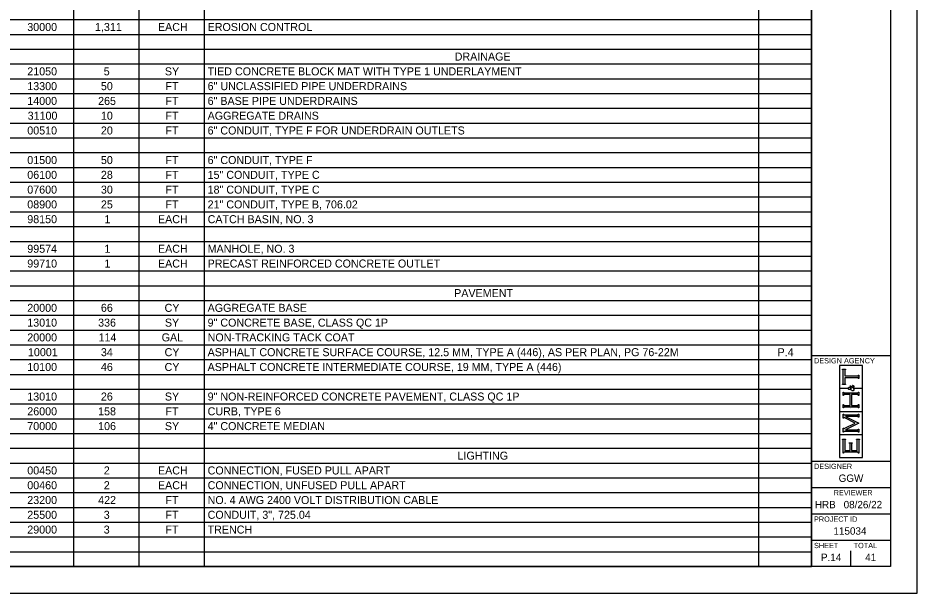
# Model space of a CAD drawing. Extents: x 0 to 34, y 0 to 22.
# Drawn here: x 16.98 to 34, y 0 to 10.89 of the extents above; entities that cross this region are included whole.
import ezdxf

# ---------------------------------------------------------------- set-up
doc = ezdxf.new("R2010")
doc.units = 0
for name, color, linetype in [('SH_Border', 7, 'Continuous'), ('SH_Cut_Line', 7, 'Continuous'), ('SH_Data', 7, 'Continuous'), ('SH_Text', 7, 'Continuous')]:
    doc.layers.add(name, color=color, linetype=linetype)

msp = doc.modelspace()

# ---------------------------------------------------------------- linework, layer by layer
at = {"layer": 'SH_Border'}
for p, q in [((32, 0.5), (32, 21.5)), ((32, 4.5), (33.5, 4.5)), ((32, 2.5), (33.5, 2.5)), ((32, 2), (33.5, 2)), ((32, 1.5), (33.5, 1.5)), ((32, 1), (33.5, 1))]:
    msp.add_line(p, q, dxfattribs=at)
msp.add_lwpolyline([(1.5, 21.5), (33.5, 21.5), (33.5, 0.5), (1.5, 0.5)], close=True, dxfattribs=at)
at = {"layer": 'SH_Cut_Line'}
msp.add_lwpolyline([(0, 0), (34, 0), (34, 22), (0, 22)], close=True, dxfattribs=at)
at = {"layer": 'SH_Data'}
for p, q in [((32.966, 4.31), (32.534, 4.31)), ((32.534, 4.31), (32.534, 3.878)), ((32.966, 3.878), (32.966, 4.31)), ((32.588, 4.23), (32.588, 4.237)), ((32.588, 4.237), (32.644, 4.237)), ((32.594, 4.228), (32.588, 4.23)), ((32.598, 4.227), (32.594, 4.228)), ((32.599, 4.224), (32.598, 4.227)), ((32.601, 4.221), (32.599, 4.224)), ((32.602, 4.217), (32.601, 4.221)), ((32.602, 4.211), (32.602, 4.217)), ((32.602, 3.977), (32.602, 4.211)), ((32.632, 4.221), (32.631, 4.217)), ((32.631, 4.217), (32.631, 4.211)), ((32.631, 4.211), (32.631, 4.111)), ((32.631, 4.111), (32.872, 4.111)), ((32.633, 4.224), (32.632, 4.221)), ((32.635, 4.227), (32.633, 4.224)), ((32.639, 4.228), (32.635, 4.227)), ((32.644, 4.23), (32.639, 4.228)), ((32.644, 4.237), (32.644, 4.23)), ((32.872, 4.111), (32.878, 4.111)), ((32.878, 4.111), (32.882, 4.112)), ((32.882, 4.112), (32.885, 4.114)), ((32.885, 4.114), (32.887, 4.116)), ((32.887, 4.116), (32.889, 4.12)), ((32.889, 4.12), (32.891, 4.125)), ((32.891, 4.125), (32.898, 4.125)), ((32.898, 4.125), (32.898, 4.063)), ((32.588, 3.959), (32.594, 3.96)), ((32.588, 3.952), (32.588, 3.959)), ((32.644, 3.952), (32.588, 3.952)), ((32.594, 3.96), (32.598, 3.962)), ((32.598, 3.962), (32.599, 3.964)), ((32.599, 3.964), (32.601, 3.967)), ((32.601, 3.967), (32.602, 3.971)), ((32.602, 3.971), (32.602, 3.977)), ((32.872, 4.077), (32.631, 4.077)), ((32.631, 4.077), (32.631, 3.977)), ((32.631, 3.977), (32.631, 3.971)), ((32.631, 3.971), (32.632, 3.967)), ((32.632, 3.967), (32.633, 3.964)), ((32.633, 3.964), (32.635, 3.962)), ((32.635, 3.962), (32.639, 3.96)), ((32.639, 3.96), (32.644, 3.959)), ((32.644, 3.959), (32.644, 3.952)), ((32.738, 3.898), (32.738, 3.928)), ((32.738, 3.928), (32.741, 3.928)), ((32.741, 3.928), (32.741, 3.924)), ((32.741, 3.924), (32.742, 3.921)), ((32.742, 3.921), (32.744, 3.919)), ((32.744, 3.919), (32.745, 3.917)), ((32.745, 3.917), (32.75, 3.914)), ((32.781, 3.93), (32.783, 3.933)), ((32.785, 3.929), (32.781, 3.93)), ((32.783, 3.933), (32.79, 3.931)), ((32.788, 3.927), (32.785, 3.929)), ((32.789, 3.925), (32.788, 3.927)), ((32.791, 3.923), (32.789, 3.925)), ((32.79, 3.931), (32.795, 3.928)), ((32.792, 3.92), (32.791, 3.923)), ((32.792, 3.917), (32.792, 3.92)), ((32.792, 3.913), (32.792, 3.917)), ((32.795, 3.928), (32.799, 3.924)), ((32.799, 3.924), (32.802, 3.92)), ((32.802, 3.92), (32.803, 3.916)), ((32.803, 3.916), (32.803, 3.91)), ((32.878, 4.077), (32.872, 4.077)), ((32.883, 4.076), (32.878, 4.077)), ((32.885, 4.074), (32.883, 4.076)), ((32.888, 4.073), (32.885, 4.074)), ((32.889, 4.069), (32.888, 4.073)), ((32.891, 4.063), (32.889, 4.069)), ((32.898, 4.063), (32.891, 4.063)), ((32.534, 3.878), (32.693, 3.878)), ((32.693, 3.873), (32.534, 3.873)), ((32.534, 3.873), (32.534, 3.441)), ((32.602, 3.744), (32.602, 3.806)), ((32.602, 3.806), (32.609, 3.806)), ((32.609, 3.744), (32.602, 3.744)), ((32.609, 3.806), (32.611, 3.801)), ((32.61, 3.75), (32.609, 3.744)), ((32.612, 3.754), (32.61, 3.75)), ((32.611, 3.801), (32.612, 3.797)), ((32.612, 3.797), (32.615, 3.795)), ((32.615, 3.755), (32.612, 3.754)), ((32.615, 3.795), (32.617, 3.793)), ((32.617, 3.757), (32.615, 3.755)), ((32.617, 3.793), (32.622, 3.792)), ((32.622, 3.758), (32.617, 3.757)), ((32.622, 3.792), (32.628, 3.792)), ((32.628, 3.758), (32.622, 3.758)), ((32.628, 3.792), (32.872, 3.792)), ((32.732, 3.758), (32.628, 3.758)), ((32.693, 3.878), (32.693, 3.873)), ((32.701, 3.883), (32.703, 3.887)), ((32.701, 3.877), (32.701, 3.883)), ((32.701, 3.871), (32.701, 3.877)), ((32.703, 3.865), (32.701, 3.871)), ((32.703, 3.887), (32.706, 3.891)), ((32.706, 3.861), (32.703, 3.865)), ((32.706, 3.891), (32.71, 3.894)), ((32.71, 3.855), (32.706, 3.861)), ((32.71, 3.894), (32.714, 3.896)), ((32.717, 3.852), (32.71, 3.855)), ((32.714, 3.896), (32.719, 3.896)), ((32.725, 3.852), (32.717, 3.852)), ((32.719, 3.896), (32.724, 3.896)), ((32.724, 3.896), (32.728, 3.895)), ((32.728, 3.852), (32.725, 3.852)), ((32.728, 3.895), (32.732, 3.891)), ((32.731, 3.852), (32.728, 3.852)), ((32.734, 3.853), (32.731, 3.852)), ((32.732, 3.891), (32.736, 3.887)), ((32.732, 3.555), (32.732, 3.758)), ((32.737, 3.854), (32.734, 3.853)), ((32.736, 3.887), (32.74, 3.881)), ((32.741, 3.855), (32.737, 3.854)), ((32.741, 3.898), (32.738, 3.898)), ((32.74, 3.881), (32.745, 3.872)), ((32.742, 3.901), (32.741, 3.9)), ((32.741, 3.9), (32.741, 3.898)), ((32.746, 3.857), (32.741, 3.855)), ((32.743, 3.902), (32.742, 3.901)), ((32.745, 3.904), (32.743, 3.902)), ((32.747, 3.905), (32.745, 3.904)), ((32.745, 3.872), (32.755, 3.879)), ((32.753, 3.846), (32.746, 3.857)), ((32.749, 3.905), (32.747, 3.905)), ((32.756, 3.905), (32.749, 3.905)), ((32.75, 3.914), (32.757, 3.91)), ((32.759, 3.838), (32.753, 3.846)), ((32.755, 3.879), (32.765, 3.885)), ((32.764, 3.9), (32.756, 3.905)), ((32.757, 3.91), (32.765, 3.905)), ((32.765, 3.834), (32.759, 3.838)), ((32.872, 3.758), (32.76, 3.758)), ((32.76, 3.758), (32.76, 3.555)), ((32.775, 3.892), (32.764, 3.9)), ((32.765, 3.905), (32.772, 3.9)), ((32.765, 3.885), (32.775, 3.892)), ((32.77, 3.83), (32.765, 3.834)), ((32.776, 3.828), (32.77, 3.83)), ((32.772, 3.9), (32.779, 3.895)), ((32.782, 3.828), (32.776, 3.828)), ((32.779, 3.895), (32.784, 3.899)), ((32.788, 3.828), (32.782, 3.828)), ((32.784, 3.899), (32.787, 3.903)), ((32.787, 3.903), (32.789, 3.907)), ((32.793, 3.83), (32.788, 3.828)), ((32.789, 3.907), (32.791, 3.91)), ((32.794, 3.89), (32.789, 3.885)), ((32.789, 3.885), (32.795, 3.879)), ((32.791, 3.91), (32.792, 3.913)), ((32.797, 3.835), (32.793, 3.83)), ((32.798, 3.894), (32.794, 3.89)), ((32.795, 3.879), (32.798, 3.874)), ((32.801, 3.839), (32.797, 3.835)), ((32.8, 3.898), (32.798, 3.894)), ((32.798, 3.874), (32.8, 3.869)), ((32.802, 3.902), (32.8, 3.898)), ((32.8, 3.869), (32.802, 3.864)), ((32.803, 3.846), (32.801, 3.839)), ((32.803, 3.906), (32.802, 3.902)), ((32.802, 3.864), (32.803, 3.859)), ((32.803, 3.91), (32.803, 3.906)), ((32.807, 3.873), (32.803, 3.878)), ((32.803, 3.878), (32.966, 3.878)), ((32.803, 3.859), (32.803, 3.854)), ((32.803, 3.854), (32.803, 3.846)), ((32.966, 3.873), (32.807, 3.873)), ((32.872, 3.792), (32.878, 3.792)), ((32.878, 3.758), (32.872, 3.758)), ((32.878, 3.792), (32.882, 3.793)), ((32.883, 3.757), (32.878, 3.758)), ((32.882, 3.793), (32.885, 3.795)), ((32.885, 3.755), (32.883, 3.757)), ((32.885, 3.795), (32.887, 3.797)), ((32.888, 3.754), (32.885, 3.755)), ((32.887, 3.797), (32.889, 3.801)), ((32.889, 3.75), (32.888, 3.754)), ((32.889, 3.801), (32.891, 3.806)), ((32.891, 3.744), (32.889, 3.75)), ((32.891, 3.806), (32.898, 3.806)), ((32.898, 3.744), (32.891, 3.744)), ((32.898, 3.806), (32.898, 3.744)), ((32.966, 3.441), (32.966, 3.873)), ((32.534, 3.441), (32.966, 3.441)), ((32.966, 3.435), (32.534, 3.435)), ((32.534, 3.435), (32.534, 3.003)), ((32.602, 3.507), (32.602, 3.569)), ((32.602, 3.569), (32.609, 3.569)), ((32.609, 3.507), (32.602, 3.507)), ((32.609, 3.569), (32.611, 3.563)), ((32.61, 3.513), (32.609, 3.507)), ((32.612, 3.516), (32.61, 3.513)), ((32.611, 3.563), (32.612, 3.56)), ((32.612, 3.56), (32.615, 3.558)), ((32.615, 3.518), (32.612, 3.516)), ((32.615, 3.558), (32.617, 3.556)), ((32.617, 3.52), (32.615, 3.518)), ((32.617, 3.556), (32.622, 3.555)), ((32.622, 3.521), (32.617, 3.52)), ((32.622, 3.555), (32.628, 3.555)), ((32.628, 3.521), (32.622, 3.521)), ((32.628, 3.555), (32.732, 3.555)), ((32.872, 3.521), (32.628, 3.521)), ((32.75, 3.5), (32.75, 3.5)), ((32.76, 3.555), (32.872, 3.555)), ((32.872, 3.555), (32.878, 3.555)), ((32.878, 3.521), (32.872, 3.521)), ((32.878, 3.555), (32.883, 3.556)), ((32.883, 3.52), (32.878, 3.521)), ((32.883, 3.556), (32.885, 3.558)), ((32.885, 3.518), (32.883, 3.52)), ((32.885, 3.558), (32.888, 3.559)), ((32.887, 3.517), (32.885, 3.518)), ((32.888, 3.559), (32.889, 3.563)), ((32.889, 3.513), (32.887, 3.517)), ((32.889, 3.563), (32.891, 3.569)), ((32.891, 3.507), (32.889, 3.513)), ((32.891, 3.569), (32.898, 3.569)), ((32.898, 3.507), (32.891, 3.507)), ((32.898, 3.569), (32.898, 3.507)), ((32.966, 3.003), (32.966, 3.435)), ((32.602, 3.313), (32.602, 3.39)), ((32.602, 3.39), (32.609, 3.39)), ((32.609, 3.313), (32.602, 3.313)), ((32.609, 3.39), (32.611, 3.385)), ((32.612, 3.32), (32.609, 3.313)), ((32.611, 3.385), (32.612, 3.381)), ((32.612, 3.381), (32.615, 3.379)), ((32.615, 3.324), (32.612, 3.32)), ((32.615, 3.379), (32.617, 3.377)), ((32.618, 3.324), (32.615, 3.324)), ((32.617, 3.377), (32.622, 3.376)), ((32.621, 3.324), (32.618, 3.324)), ((32.626, 3.322), (32.621, 3.324)), ((32.622, 3.376), (32.628, 3.376)), ((32.633, 3.318), (32.626, 3.322)), ((32.628, 3.376), (32.872, 3.376)), ((32.831, 3.219), (32.633, 3.318)), ((32.872, 3.343), (32.649, 3.343)), ((32.649, 3.343), (32.898, 3.217)), ((32.872, 3.376), (32.878, 3.376)), ((32.878, 3.343), (32.872, 3.343)), ((32.878, 3.376), (32.882, 3.377)), ((32.883, 3.342), (32.878, 3.343)), ((32.882, 3.377), (32.885, 3.379)), ((32.885, 3.34), (32.883, 3.342)), ((32.885, 3.379), (32.887, 3.381)), ((32.887, 3.338), (32.885, 3.34)), ((32.887, 3.381), (32.889, 3.385)), ((32.889, 3.334), (32.887, 3.338)), ((32.889, 3.385), (32.891, 3.39)), ((32.891, 3.329), (32.889, 3.334)), ((32.891, 3.39), (32.898, 3.39)), ((32.898, 3.329), (32.891, 3.329)), ((32.898, 3.39), (32.898, 3.329)), ((32.602, 3.048), (32.602, 3.124)), ((32.602, 3.124), (32.609, 3.124)), ((32.609, 3.124), (32.612, 3.117)), ((32.612, 3.117), (32.615, 3.114)), ((32.615, 3.114), (32.618, 3.114)), ((32.618, 3.114), (32.62, 3.114)), ((32.62, 3.114), (32.625, 3.116)), ((32.625, 3.116), (32.635, 3.121)), ((32.635, 3.121), (32.831, 3.219)), ((32.898, 3.217), (32.649, 3.092)), ((32.649, 3.092), (32.872, 3.092)), ((32.872, 3.092), (32.878, 3.092)), ((32.878, 3.092), (32.882, 3.093)), ((32.882, 3.093), (32.885, 3.095)), ((32.885, 3.095), (32.887, 3.097)), ((32.887, 3.097), (32.889, 3.101)), ((32.889, 3.101), (32.891, 3.106)), ((32.891, 3.106), (32.898, 3.106)), ((32.898, 3.106), (32.898, 3.048)), ((32.534, 3.003), (32.966, 3.003)), ((32.966, 2.997), (32.534, 2.997)), ((32.534, 2.997), (32.534, 2.566)), ((32.588, 2.905), (32.588, 2.912)), ((32.588, 2.912), (32.644, 2.912)), ((32.594, 2.903), (32.588, 2.905)), ((32.598, 2.901), (32.594, 2.903)), ((32.599, 2.899), (32.598, 2.901)), ((32.601, 2.896), (32.599, 2.899)), ((32.602, 2.892), (32.601, 2.896)), ((32.609, 3.048), (32.602, 3.048)), ((32.61, 3.053), (32.609, 3.048)), ((32.612, 3.057), (32.61, 3.053)), ((32.615, 3.059), (32.612, 3.057)), ((32.617, 3.061), (32.615, 3.059)), ((32.622, 3.062), (32.617, 3.061)), ((32.628, 3.062), (32.622, 3.062)), ((32.872, 3.062), (32.628, 3.062)), ((32.632, 2.896), (32.631, 2.892)), ((32.633, 2.899), (32.632, 2.896)), ((32.635, 2.901), (32.633, 2.899)), ((32.639, 2.903), (32.635, 2.901)), ((32.644, 2.905), (32.639, 2.903)), ((32.644, 2.912), (32.644, 2.905)), ((32.855, 2.908), (32.855, 2.915)), ((32.855, 2.915), (32.912, 2.915)), ((32.861, 2.906), (32.855, 2.908)), ((32.865, 2.904), (32.861, 2.906)), ((32.867, 2.902), (32.865, 2.904)), ((32.868, 2.899), (32.867, 2.902)), ((32.869, 2.895), (32.868, 2.899)), ((32.869, 2.889), (32.869, 2.895)), ((32.878, 3.062), (32.872, 3.062)), ((32.883, 3.061), (32.878, 3.062)), ((32.885, 3.059), (32.883, 3.061)), ((32.887, 3.057), (32.885, 3.059)), ((32.889, 3.053), (32.887, 3.057)), ((32.891, 3.048), (32.889, 3.053)), ((32.898, 3.048), (32.891, 3.048)), ((32.899, 2.899), (32.898, 2.895)), ((32.898, 2.895), (32.898, 2.889)), ((32.901, 2.902), (32.899, 2.899)), ((32.903, 2.904), (32.901, 2.902)), ((32.906, 2.906), (32.903, 2.904)), ((32.912, 2.908), (32.906, 2.906)), ((32.912, 2.915), (32.912, 2.908)), ((32.966, 2.566), (32.966, 2.997)), ((32.602, 2.886), (32.602, 2.892)), ((32.602, 2.651), (32.602, 2.886)), ((32.631, 2.892), (32.631, 2.886)), ((32.631, 2.886), (32.631, 2.699)), ((32.718, 2.84), (32.718, 2.847)), ((32.718, 2.847), (32.774, 2.847)), ((32.723, 2.839), (32.718, 2.84)), ((32.727, 2.837), (32.723, 2.839)), ((32.729, 2.834), (32.727, 2.837)), ((32.731, 2.832), (32.729, 2.834)), ((32.732, 2.827), (32.731, 2.832)), ((32.732, 2.821), (32.732, 2.827)), ((32.732, 2.699), (32.732, 2.821)), ((32.761, 2.832), (32.76, 2.827)), ((32.76, 2.827), (32.76, 2.821)), ((32.76, 2.821), (32.76, 2.699)), ((32.763, 2.834), (32.761, 2.832)), ((32.765, 2.837), (32.763, 2.834)), ((32.768, 2.839), (32.765, 2.837)), ((32.774, 2.84), (32.768, 2.839)), ((32.774, 2.847), (32.774, 2.84)), ((32.869, 2.699), (32.869, 2.889)), ((32.898, 2.889), (32.898, 2.651)), ((32.534, 2.566), (32.966, 2.566)), ((32.609, 2.651), (32.602, 2.651)), ((32.611, 2.657), (32.609, 2.651)), ((32.612, 2.66), (32.611, 2.657)), ((32.615, 2.662), (32.612, 2.66)), ((32.617, 2.664), (32.615, 2.662)), ((32.622, 2.665), (32.617, 2.664)), ((32.628, 2.665), (32.622, 2.665)), ((32.872, 2.665), (32.628, 2.665)), ((32.631, 2.699), (32.732, 2.699)), ((32.76, 2.699), (32.869, 2.699)), ((32.878, 2.665), (32.872, 2.665)), ((32.883, 2.664), (32.878, 2.665)), ((32.885, 2.662), (32.883, 2.664)), ((32.887, 2.661), (32.885, 2.662)), ((32.889, 2.657), (32.887, 2.661)), ((32.891, 2.651), (32.889, 2.657)), ((32.898, 2.651), (32.891, 2.651)), ((32.75, 0.5), (32.75, 0.8)), ((32.375, 0.675), (32.375, 0.675))]:
    msp.add_line(p, q, dxfattribs=at)
at = {"layer": 'SH_Text'}
for p, q in [((18.035, 21.5), (18.035, 0.502)), ((19.27, 21.5), (19.27, 0.502)), ((20.506, 21.5), (20.506, 0.502)), ((30.997, 21.5), (30.997, 0.502)), ((32.001, 21.5), (32.001, 0.502)), ((1.5, 10.861), (32.001, 10.861)), ((1.5, 10.581), (32.001, 10.581)), ((1.5, 10.301), (32.001, 10.301)), ((1.5, 10.021), (32.001, 10.021)), ((1.5, 9.741), (32.001, 9.741)), ((1.5, 9.461), (32.001, 9.461)), ((1.5, 9.181), (32.001, 9.181)), ((1.5, 8.901), (32.001, 8.901)), ((1.5, 8.621), (32.001, 8.621)), ((1.5, 8.341), (32.001, 8.341)), ((1.5, 8.061), (32.001, 8.061)), ((1.5, 7.781), (32.001, 7.781)), ((1.5, 7.501), (32.001, 7.501)), ((1.5, 7.221), (32.001, 7.221)), ((1.5, 6.941), (32.001, 6.941)), ((1.5, 6.661), (32.001, 6.661)), ((1.5, 6.381), (32.001, 6.381)), ((1.5, 6.101), (32.001, 6.101)), ((1.5, 5.821), (32.001, 5.821)), ((1.5, 5.541), (32.001, 5.541)), ((1.5, 5.261), (32.001, 5.261)), ((1.5, 4.981), (32.001, 4.981)), ((1.5, 4.701), (32.001, 4.701)), ((1.5, 4.421), (32.001, 4.421)), ((1.5, 4.141), (32.001, 4.141)), ((1.5, 3.861), (32.001, 3.861)), ((1.5, 3.581), (32.001, 3.581)), ((1.5, 3.301), (32.001, 3.301)), ((1.5, 3.021), (32.001, 3.021)), ((1.5, 2.741), (32.001, 2.741)), ((1.5, 2.461), (32.001, 2.461)), ((1.5, 2.182), (32.001, 2.182)), ((1.5, 1.902), (32.001, 1.902)), ((1.5, 1.622), (32.001, 1.622)), ((1.5, 1.342), (32.001, 1.342)), ((1.5, 1.062), (32.001, 1.062)), ((1.5, 0.782), (32.001, 0.782)), ((1.5, 0.502), (32.001, 0.502))]:
    msp.add_line(p, q, dxfattribs=at)

# ---------------------------------------------------------------- texts
at = {"layer": 'SH_Data'}
for s, height, p in [('DESIGN AGENCY', 0.1, (32.05, 4.35)), ('DESIGNER', 0.1, (32.05, 2.35)), ('GGW', 0.14, (32.516, 2.105)), ('REVIEWER', 0.1, (32.422, 1.85)), ('HRB', 0.14, (32.066, 1.605)), ('08/26/22', 0.14, (32.611, 1.605)), ('PROJECT ID', 0.1, (32.05, 1.35)), ('115034', 0.14, (32.418, 1.105)), ('SHEET', 0.1, (32.05, 0.85)), ('TOTAL', 0.1, (32.8, 0.85)), ('P.14', 0.14, (32.182, 0.605)), ('41', 0.14, (33.019, 0.605))]:
    msp.add_text(s, height=height, dxfattribs=at).set_placement(p)
at = {"layer": 'SH_Text'}
for s, height, p in [('30000', 0.1515, (17.157, 10.645)), ('1,311', 0.1515, (18.439, 10.645)), ('EACH', 0.1515, (19.631, 10.645)), ('EROSION CONTROL', 0.15152, (20.571, 10.645)), ('DRAINAGE', 0.1515, (25.248, 10.085)), ('21050', 0.1515, (17.157, 9.805)), ('5', 0.152, (18.604, 9.805)), ('SY', 0.1515, (19.762, 9.805)), ('TIED CONCRETE BLOCK MAT WITH TYPE 1 UNDERLAYMENT', 0.15152, (20.571, 9.805)), ('13300', 0.1515, (17.157, 9.525)), ('50', 0.1515, (18.551, 9.525)), ('FT', 0.1515, (19.773, 9.525)), ('6" UNCLASSIFIED PIPE UNDERDRAINS', 0.15152, (20.571, 9.525)), ('14000', 0.1515, (17.157, 9.245)), ('265', 0.1515, (18.498, 9.245)), ('FT', 0.1515, (19.773, 9.245)), ('6" BASE PIPE UNDERDRAINS', 0.15152, (20.571, 9.245)), ('31100', 0.1515, (17.164, 8.965)), ('10', 0.1515, (18.551, 8.965)), ('FT', 0.1515, (19.773, 8.965)), ('AGGREGATE DRAINS', 0.15152, (20.571, 8.965)), ('00510', 0.1515, (17.157, 8.685)), ('20', 0.1515, (18.551, 8.685)), ('FT', 0.1515, (19.773, 8.685)), ('6" CONDUIT, TYPE F FOR UNDERDRAIN OUTLETS', 0.15152, (20.571, 8.685)), ('01500', 0.1515, (17.157, 8.125)), ('50', 0.1515, (18.551, 8.125)), ('FT', 0.1515, (19.773, 8.125)), ('6" CONDUIT, TYPE F', 0.15152, (20.571, 8.125)), ('06100', 0.1515, (17.157, 7.845)), ('28', 0.1515, (18.551, 7.845)), ('15" CONDUIT, TYPE C', 0.15152, (20.571, 7.845)), ('FT', 0.1515, (19.773, 7.845)), ('07600', 0.1515, (17.157, 7.565)), ('30', 0.1515, (18.551, 7.565)), ('FT', 0.1515, (19.773, 7.565)), ('18" CONDUIT, TYPE C', 0.15152, (20.571, 7.565)), ('08900', 0.1515, (17.157, 7.285)), ('25', 0.1515, (18.551, 7.285)), ('FT', 0.1515, (19.773, 7.285)), ('21" CONDUIT, TYPE B, 706.02', 0.15152, (20.571, 7.285)), ('98150', 0.1515, (17.157, 7.005)), ('1', 0.152, (18.617, 7.005)), ('EACH', 0.1515, (19.631, 7.005)), ('CATCH BASIN, NO. 3', 0.15152, (20.571, 7.005)), ('99574', 0.1515, (17.157, 6.445)), ('1', 0.152, (18.617, 6.445)), ('EACH', 0.1515, (19.631, 6.445)), ('MANHOLE, NO. 3', 0.15152, (20.571, 6.445)), ('99710', 0.1515, (17.157, 6.165)), ('1', 0.152, (18.617, 6.165)), ('EACH', 0.1515, (19.631, 6.165)), ('PRECAST REINFORCED CONCRETE OUTLET', 0.15152, (20.571, 6.165)), ('PAVEMENT', 0.1515, (25.238, 5.605)), ('20000', 0.1515, (17.157, 5.326)), ('66', 0.1515, (18.551, 5.326)), ('CY', 0.1515, (19.756, 5.326)), ('AGGREGATE BASE', 0.15152, (20.571, 5.326)), ('13010', 0.1515, (17.157, 5.046)), ('336', 0.1515, (18.498, 5.046)), ('SY', 0.1515, (19.762, 5.046)), ('9" CONCRETE BASE, CLASS QC 1P', 0.15152, (20.571, 5.046)), ('20000', 0.1515, (17.157, 4.766)), ('114', 0.1515, (18.506, 4.766)), ('GAL', 0.1515, (19.701, 4.766)), ('NON-TRACKING TACK COAT', 0.15152, (20.571, 4.766)), ('10001', 0.1515, (17.17, 4.486)), ('34', 0.1515, (18.551, 4.486)), ('CY', 0.1515, (19.756, 4.486)), ('ASPHALT CONCRETE SURFACE COURSE, 12.5 MM, TYPE A (446), AS PER PLAN, PG 76-22M', 0.15152, (20.571, 4.486)), ('P.4', 0.1515, (31.36, 4.486)), ('10100', 0.1515, (17.157, 4.206)), ('46', 0.1515, (18.551, 4.206)), ('CY', 0.1515, (19.756, 4.206)), ('ASPHALT CONCRETE INTERMEDIATE COURSE, 19 MM, TYPE A (446)', 0.15152, (20.571, 4.206)), ('13010', 0.1515, (17.157, 3.646)), ('26', 0.1515, (18.551, 3.646)), ('SY', 0.1515, (19.762, 3.646)), ('9" NON-REINFORCED CONCRETE PAVEMENT, CLASS QC 1P', 0.15152, (20.571, 3.646)), ('26000', 0.1515, (17.157, 3.366)), ('158', 0.1515, (18.498, 3.366)), ('FT', 0.1515, (19.773, 3.366)), ('CURB, TYPE 6', 0.15152, (20.571, 3.366)), ('70000', 0.1515, (17.157, 3.086)), ('106', 0.1515, (18.498, 3.086)), ('SY', 0.1515, (19.762, 3.086)), ('4" CONCRETE MEDIAN', 0.15152, (20.571, 3.086)), ('LIGHTING', 0.1515, (25.302, 2.526)), ('00450', 0.1515, (17.157, 2.246)), ('2', 0.152, (18.605, 2.246)), ('EACH', 0.1515, (19.631, 2.246)), ('CONNECTION, FUSED PULL APART', 0.15152, (20.571, 2.246)), ('00460', 0.1515, (17.157, 1.966)), ('2', 0.152, (18.605, 1.966)), ('EACH', 0.1515, (19.631, 1.966)), ('CONNECTION, UNFUSED PULL APART', 0.15152, (20.571, 1.966)), ('23200', 0.1515, (17.157, 1.686)), ('422', 0.1515, (18.499, 1.686)), ('FT', 0.1515, (19.773, 1.686)), ('NO. 4 AWG 2400 VOLT DISTRIBUTION CABLE', 0.15152, (20.571, 1.686)), ('25500', 0.1515, (17.157, 1.406)), ('3', 0.152, (18.604, 1.406)), ('FT', 0.1515, (19.773, 1.406)), ('CONDUIT, 3", 725.04', 0.15152, (20.571, 1.406)), ('29000', 0.1515, (17.157, 1.126)), ('3', 0.152, (18.604, 1.126)), ('FT', 0.1515, (19.773, 1.126)), ('TRENCH', 0.1515, (20.571, 1.126))]:
    msp.add_text(s, height=height, dxfattribs=at).set_placement(p)

doc.saveas('drawing.dxf')
